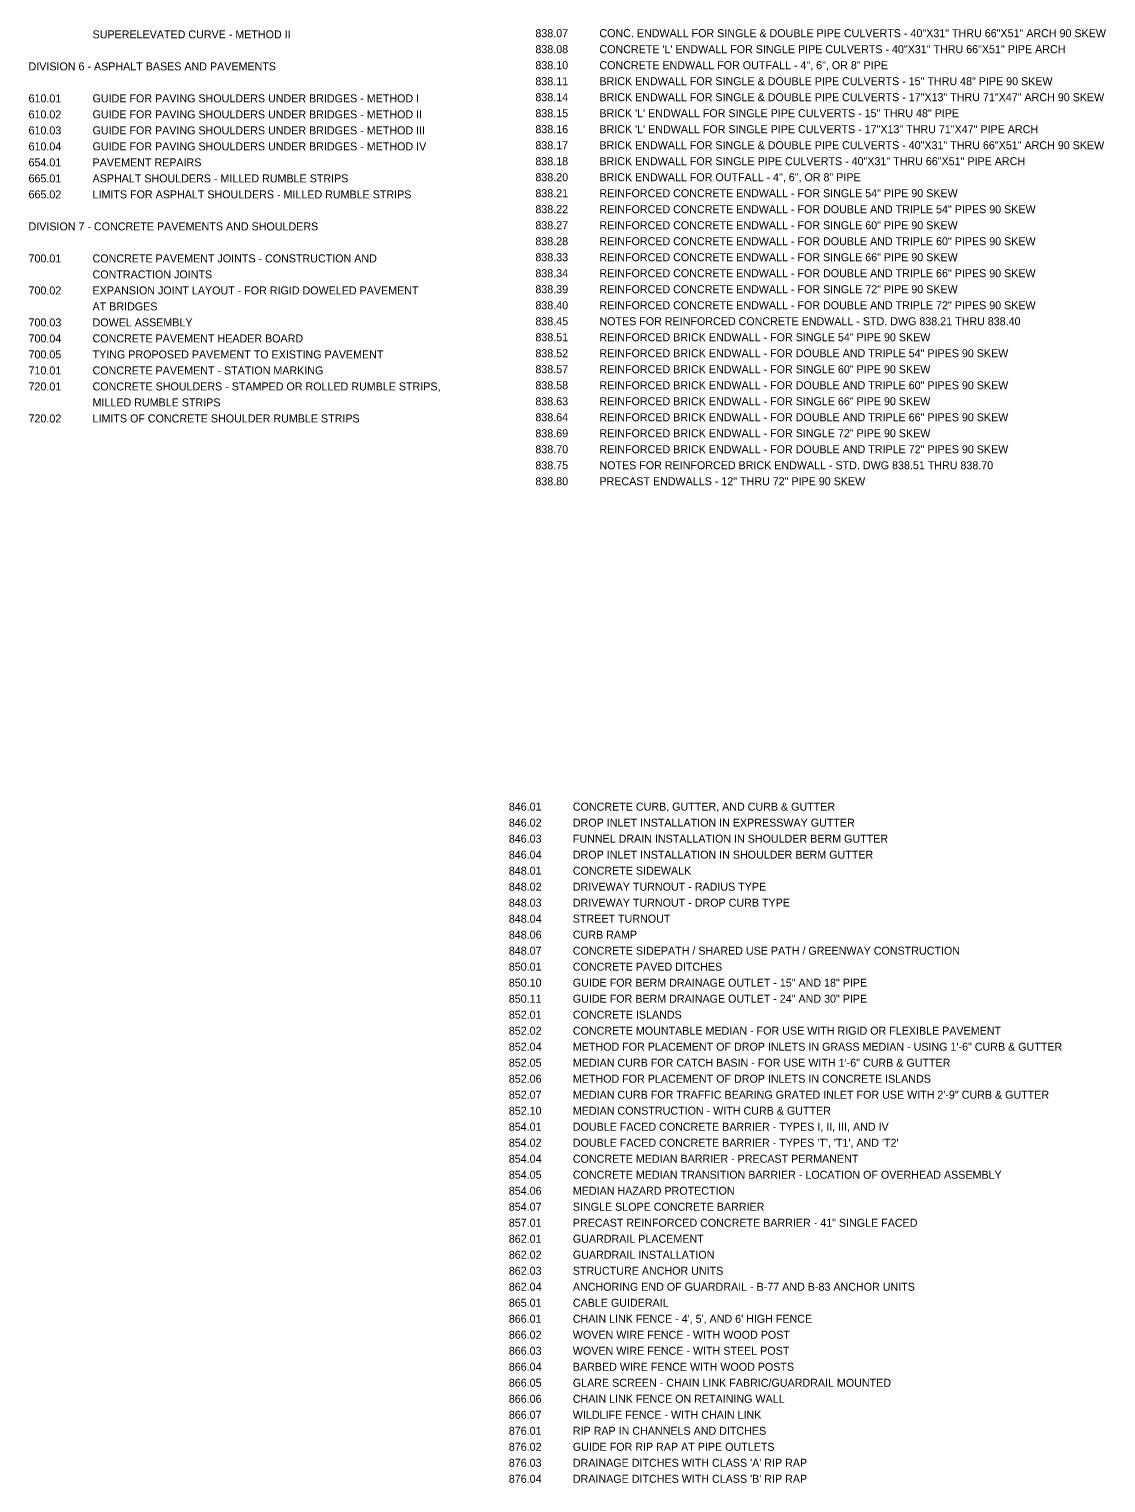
# Model space of a CAD drawing. Extents: x 573076.3 to 573113.7, y -55253.8 to -55199.3.
# Drawn here: x 573091.52 to 573111.7, y -55253.8 to -55226.55 of the extents above; entities that cross this region are included whole.
import ezdxf

# ---------------------------------------------------------------- set-up
doc = ezdxf.new("R2010")
doc.units = 0
doc.layers.add('Prop DSN Text', color=7, linetype='Continuous')

msp = doc.modelspace()

# ---------------------------------------------------------------- texts
at = {"layer": 'Prop DSN Text'}
for s, p in [('SUPERELEVATED CURVE - METHOD II', (573092.714, -55226.721)), ('838.07', (573101.012, -55226.699)), ('CONC. ENDWALL FOR SINGLE & DOUBLE PIPE CULVERTS - 40"X31" THRU 66"X51" ARCH 90 SKEW', (573102.212, -55226.699)), ('838.08', (573101.012, -55226.999)), ('CONCRETE \'L\' ENDWALL FOR SINGLE PIPE CULVERTS - 40"X31" THRU 66"X51" PIPE ARCH', (573102.212, -55226.999)), ('DIVISION 6 - ASPHALT BASES AND PAVEMENTS', (573091.514, -55227.321)), ('838.10', (573101.012, -55227.299)), ('CONCRETE ENDWALL FOR OUTFALL - 4", 6", OR 8" PIPE', (573102.212, -55227.299)), ('838.11', (573101.012, -55227.599)), ('BRICK ENDWALL FOR SINGLE & DOUBLE PIPE CULVERTS - 15" THRU 48" PIPE 90 SKEW', (573102.212, -55227.599)), ('610.01', (573091.514, -55227.921)), ('GUIDE FOR PAVING SHOULDERS UNDER BRIDGES - METHOD I', (573092.714, -55227.921)), ('838.14', (573101.012, -55227.899)), ('BRICK ENDWALL FOR SINGLE & DOUBLE PIPE CULVERTS - 17"X13" THRU 71"X47" ARCH 90 SKEW', (573102.212, -55227.899)), ('610.02', (573091.514, -55228.221)), ('GUIDE FOR PAVING SHOULDERS UNDER BRIDGES - METHOD II', (573092.714, -55228.221)), ('838.15', (573101.012, -55228.199)), ('BRICK \'L\' ENDWALL FOR SINGLE PIPE CULVERTS - 15" THRU 48" PIPE', (573102.212, -55228.199)), ('610.03', (573091.514, -55228.521)), ('GUIDE FOR PAVING SHOULDERS UNDER BRIDGES - METHOD III', (573092.714, -55228.521)), ('838.16', (573101.012, -55228.499)), ('BRICK \'L\' ENDWALL FOR SINGLE PIPE CULVERTS - 17"X13" THRU 71"X47" PIPE ARCH', (573102.212, -55228.499)), ('610.04', (573091.514, -55228.821)), ('GUIDE FOR PAVING SHOULDERS UNDER BRIDGES - METHOD IV', (573092.714, -55228.821)), ('838.17', (573101.012, -55228.799)), ('BRICK ENDWALL FOR SINGLE & DOUBLE PIPE CULVERTS - 40"X31" THRU 66"X51" ARCH 90 SKEW', (573102.212, -55228.799)), ('654.01', (573091.514, -55229.121)), ('PAVEMENT REPAIRS', (573092.714, -55229.121)), ('838.18', (573101.012, -55229.099)), ('BRICK ENDWALL FOR SINGLE PIPE CULVERTS - 40"X31" THRU 66"X51" PIPE ARCH', (573102.212, -55229.099)), ('665.01', (573091.514, -55229.421)), ('ASPHALT SHOULDERS - MILLED RUMBLE STRIPS', (573092.714, -55229.421)), ('838.20', (573101.012, -55229.399)), ('BRICK ENDWALL FOR OUTFALL - 4", 6", OR 8" PIPE', (573102.212, -55229.399)), ('665.02', (573091.514, -55229.721)), ('LIMITS FOR ASPHALT SHOULDERS - MILLED RUMBLE STRIPS', (573092.714, -55229.721)), ('838.21', (573101.012, -55229.699)), ('REINFORCED CONCRETE ENDWALL - FOR SINGLE 54" PIPE 90 SKEW', (573102.212, -55229.699)), ('838.22', (573101.012, -55229.999)), ('REINFORCED CONCRETE ENDWALL - FOR DOUBLE AND TRIPLE 54" PIPES 90 SKEW', (573102.212, -55229.999)), ('DIVISION 7 - CONCRETE PAVEMENTS AND SHOULDERS', (573091.514, -55230.321)), ('838.27', (573101.012, -55230.299)), ('REINFORCED CONCRETE ENDWALL - FOR SINGLE 60" PIPE 90 SKEW', (573102.212, -55230.299)), ('838.28', (573101.012, -55230.599)), ('REINFORCED CONCRETE ENDWALL - FOR DOUBLE AND TRIPLE 60" PIPES 90 SKEW', (573102.212, -55230.599)), ('700.01', (573091.514, -55230.921)), ('CONCRETE PAVEMENT JOINTS - CONSTRUCTION AND', (573092.714, -55230.921)), ('838.33', (573101.012, -55230.899)), ('REINFORCED CONCRETE ENDWALL - FOR SINGLE 66" PIPE 90 SKEW', (573102.212, -55230.899)), ('CONTRACTION JOINTS', (573092.714, -55231.221)), ('838.34', (573101.012, -55231.199)), ('REINFORCED CONCRETE ENDWALL - FOR DOUBLE AND TRIPLE 66" PIPES 90 SKEW', (573102.212, -55231.199)), ('700.02', (573091.514, -55231.521)), ('EXPANSION JOINT LAYOUT - FOR RIGID DOWELED PAVEMENT', (573092.714, -55231.521)), ('838.39', (573101.012, -55231.499)), ('REINFORCED CONCRETE ENDWALL - FOR SINGLE 72" PIPE 90 SKEW', (573102.212, -55231.499)), ('AT BRIDGES', (573092.714, -55231.821)), ('838.40', (573101.012, -55231.799)), ('REINFORCED CONCRETE ENDWALL - FOR DOUBLE AND TRIPLE 72" PIPES 90 SKEW', (573102.212, -55231.799)), ('700.03', (573091.514, -55232.121)), ('DOWEL ASSEMBLY', (573092.714, -55232.121)), ('838.45', (573101.012, -55232.099)), ('NOTES FOR REINFORCED CONCRETE ENDWALL - STD. DWG 838.21 THRU 838.40', (573102.212, -55232.099)), ('700.04', (573091.514, -55232.421)), ('CONCRETE PAVEMENT HEADER BOARD', (573092.714, -55232.421)), ('838.51', (573101.012, -55232.399)), ('REINFORCED BRICK ENDWALL - FOR SINGLE 54" PIPE 90 SKEW', (573102.212, -55232.399)), ('700.05', (573091.514, -55232.721)), ('TYING PROPOSED PAVEMENT TO EXISTING PAVEMENT', (573092.714, -55232.721)), ('838.52', (573101.012, -55232.699)), ('REINFORCED BRICK ENDWALL - FOR DOUBLE AND TRIPLE 54" PIPES 90 SKEW', (573102.212, -55232.699)), ('710.01', (573091.514, -55233.021)), ('CONCRETE PAVEMENT - STATION MARKING', (573092.714, -55233.021)), ('838.57', (573101.012, -55232.999)), ('REINFORCED BRICK ENDWALL - FOR SINGLE 60" PIPE 90 SKEW', (573102.212, -55232.999)), ('720.01', (573091.514, -55233.321)), ('CONCRETE SHOULDERS - STAMPED OR ROLLED RUMBLE STRIPS,', (573092.714, -55233.321)), ('838.58', (573101.012, -55233.299)), ('REINFORCED BRICK ENDWALL - FOR DOUBLE AND TRIPLE 60" PIPES 90 SKEW', (573102.212, -55233.299)), ('838.63', (573101.012, -55233.599)), ('REINFORCED BRICK ENDWALL - FOR SINGLE 66" PIPE 90 SKEW', (573102.212, -55233.599)), ('MILLED RUMBLE STRIPS', (573092.714, -55233.621)), ('720.02', (573091.514, -55233.921)), ('LIMITS OF CONCRETE SHOULDER RUMBLE STRIPS', (573092.714, -55233.921)), ('838.64', (573101.012, -55233.899)), ('REINFORCED BRICK ENDWALL - FOR DOUBLE AND TRIPLE 66" PIPES 90 SKEW', (573102.212, -55233.899)), ('838.69', (573101.012, -55234.199)), ('REINFORCED BRICK ENDWALL - FOR SINGLE 72" PIPE 90 SKEW', (573102.212, -55234.199)), ('838.70', (573101.012, -55234.499)), ('REINFORCED BRICK ENDWALL - FOR DOUBLE AND TRIPLE 72" PIPES 90 SKEW', (573102.212, -55234.499)), ('838.75', (573101.012, -55234.799)), ('NOTES FOR REINFORCED BRICK ENDWALL - STD. DWG 838.51 THRU 838.70', (573102.212, -55234.799)), ('838.80', (573101.012, -55235.099)), ('PRECAST ENDWALLS - 12" THRU 72" PIPE 90 SKEW', (573102.212, -55235.099)), ('846.01', (573100.514, -55241.199)), ('CONCRETE CURB, GUTTER, AND CURB & GUTTER', (573101.714, -55241.199)), ('846.02', (573100.514, -55241.499)), ('DROP INLET INSTALLATION IN EXPRESSWAY GUTTER', (573101.714, -55241.499)), ('846.03', (573100.514, -55241.799)), ('FUNNEL DRAIN INSTALLATION IN SHOULDER BERM GUTTER', (573101.714, -55241.799)), ('846.04', (573100.514, -55242.099)), ('DROP INLET INSTALLATION IN SHOULDER BERM GUTTER', (573101.714, -55242.099)), ('848.01', (573100.514, -55242.399)), ('CONCRETE SIDEWALK', (573101.714, -55242.399)), ('848.02', (573100.514, -55242.699)), ('DRIVEWAY TURNOUT - RADIUS TYPE', (573101.714, -55242.699)), ('848.03', (573100.514, -55242.999)), ('DRIVEWAY TURNOUT - DROP CURB TYPE', (573101.714, -55242.999)), ('848.04', (573100.514, -55243.299)), ('STREET TURNOUT', (573101.714, -55243.299)), ('848.06', (573100.514, -55243.599)), ('CURB RAMP', (573101.714, -55243.599)), ('848.07', (573100.514, -55243.899)), ('CONCRETE SIDEPATH / SHARED USE PATH / GREENWAY CONSTRUCTION', (573101.714, -55243.899)), ('850.01', (573100.514, -55244.199)), ('CONCRETE PAVED DITCHES', (573101.714, -55244.199)), ('850.10', (573100.514, -55244.499)), ('GUIDE FOR BERM DRAINAGE OUTLET - 15" AND 18" PIPE', (573101.714, -55244.499)), ('850.11', (573100.514, -55244.799)), ('GUIDE FOR BERM DRAINAGE OUTLET - 24" AND 30" PIPE', (573101.714, -55244.799)), ('852.01', (573100.514, -55245.099)), ('CONCRETE ISLANDS', (573101.714, -55245.099)), ('852.02', (573100.514, -55245.399)), ('CONCRETE MOUNTABLE MEDIAN - FOR USE WITH RIGID OR FLEXIBLE PAVEMENT', (573101.714, -55245.399)), ('852.04', (573100.514, -55245.699)), ('METHOD FOR PLACEMENT OF DROP INLETS IN GRASS MEDIAN - USING 1\'-6" CURB & GUTTER', (573101.714, -55245.699)), ('852.05', (573100.514, -55245.999)), ('MEDIAN CURB FOR CATCH BASIN - FOR USE WITH 1\'-6" CURB & GUTTER', (573101.714, -55245.999)), ('852.06', (573100.514, -55246.299)), ('METHOD FOR PLACEMENT OF DROP INLETS IN CONCRETE ISLANDS', (573101.714, -55246.299)), ('852.07', (573100.514, -55246.599)), ('MEDIAN CURB FOR TRAFFIC BEARING GRATED INLET FOR USE WITH 2\'-9" CURB & GUTTER', (573101.714, -55246.599)), ('852.10', (573100.514, -55246.899)), ('MEDIAN CONSTRUCTION - WITH CURB & GUTTER', (573101.714, -55246.899)), ('854.01', (573100.514, -55247.199)), ('DOUBLE FACED CONCRETE BARRIER - TYPES I, II, III, AND IV', (573101.714, -55247.199)), ('854.02', (573100.514, -55247.499)), ("DOUBLE FACED CONCRETE BARRIER - TYPES 'T', 'T1', AND 'T2'", (573101.714, -55247.499)), ('854.04', (573100.514, -55247.799)), ('CONCRETE MEDIAN BARRIER - PRECAST PERMANENT', (573101.714, -55247.799)), ('854.05', (573100.514, -55248.099)), ('CONCRETE MEDIAN TRANSITION BARRIER - LOCATION OF OVERHEAD ASSEMBLY', (573101.714, -55248.099)), ('854.06', (573100.514, -55248.399)), ('MEDIAN HAZARD PROTECTION', (573101.714, -55248.399)), ('854.07', (573100.514, -55248.699)), ('SINGLE SLOPE CONCRETE BARRIER', (573101.714, -55248.699)), ('857.01', (573100.514, -55248.999)), ('PRECAST REINFORCED CONCRETE BARRIER - 41" SINGLE FACED', (573101.714, -55248.999)), ('862.01', (573100.514, -55249.299)), ('GUARDRAIL PLACEMENT', (573101.714, -55249.299)), ('862.02', (573100.514, -55249.599)), ('GUARDRAIL INSTALLATION', (573101.714, -55249.599)), ('862.03', (573100.514, -55249.899)), ('STRUCTURE ANCHOR UNITS', (573101.714, -55249.899)), ('862.04', (573100.514, -55250.199)), ('ANCHORING END OF GUARDRAIL - B-77 AND B-83 ANCHOR UNITS', (573101.714, -55250.199)), ('865.01', (573100.514, -55250.499)), ('CABLE GUIDERAIL', (573101.714, -55250.499)), ('866.01', (573100.514, -55250.799)), ("CHAIN LINK FENCE - 4', 5', AND 6' HIGH FENCE", (573101.714, -55250.799)), ('866.02', (573100.514, -55251.099)), ('WOVEN WIRE FENCE - WITH WOOD POST', (573101.714, -55251.099)), ('866.03', (573100.514, -55251.399)), ('WOVEN WIRE FENCE - WITH STEEL POST', (573101.714, -55251.399)), ('866.04', (573100.514, -55251.699)), ('BARBED WIRE FENCE WITH WOOD POSTS', (573101.714, -55251.699)), ('866.05', (573100.514, -55251.999)), ('GLARE SCREEN - CHAIN LINK FABRIC/GUARDRAIL MOUNTED', (573101.714, -55251.999)), ('866.06', (573100.514, -55252.299)), ('CHAIN LINK FENCE ON RETAINING WALL', (573101.714, -55252.299)), ('866.07', (573100.514, -55252.599)), ('WILDLIFE FENCE - WITH CHAIN LINK', (573101.714, -55252.599)), ('876.01', (573100.514, -55252.899)), ('RIP RAP IN CHANNELS AND DITCHES', (573101.714, -55252.899)), ('876.02', (573100.514, -55253.199)), ('GUIDE FOR RIP RAP AT PIPE OUTLETS', (573101.714, -55253.199)), ('876.03', (573100.514, -55253.499)), ("DRAINAGE DITCHES WITH CLASS 'A' RIP RAP", (573101.714, -55253.499)), ('876.04', (573100.514, -55253.799)), ("DRAINAGE DITCHES WITH CLASS 'B' RIP RAP", (573101.714, -55253.799))]:
    msp.add_text(s, height=0.15, dxfattribs=at).set_placement(p)

doc.saveas('drawing.dxf')
